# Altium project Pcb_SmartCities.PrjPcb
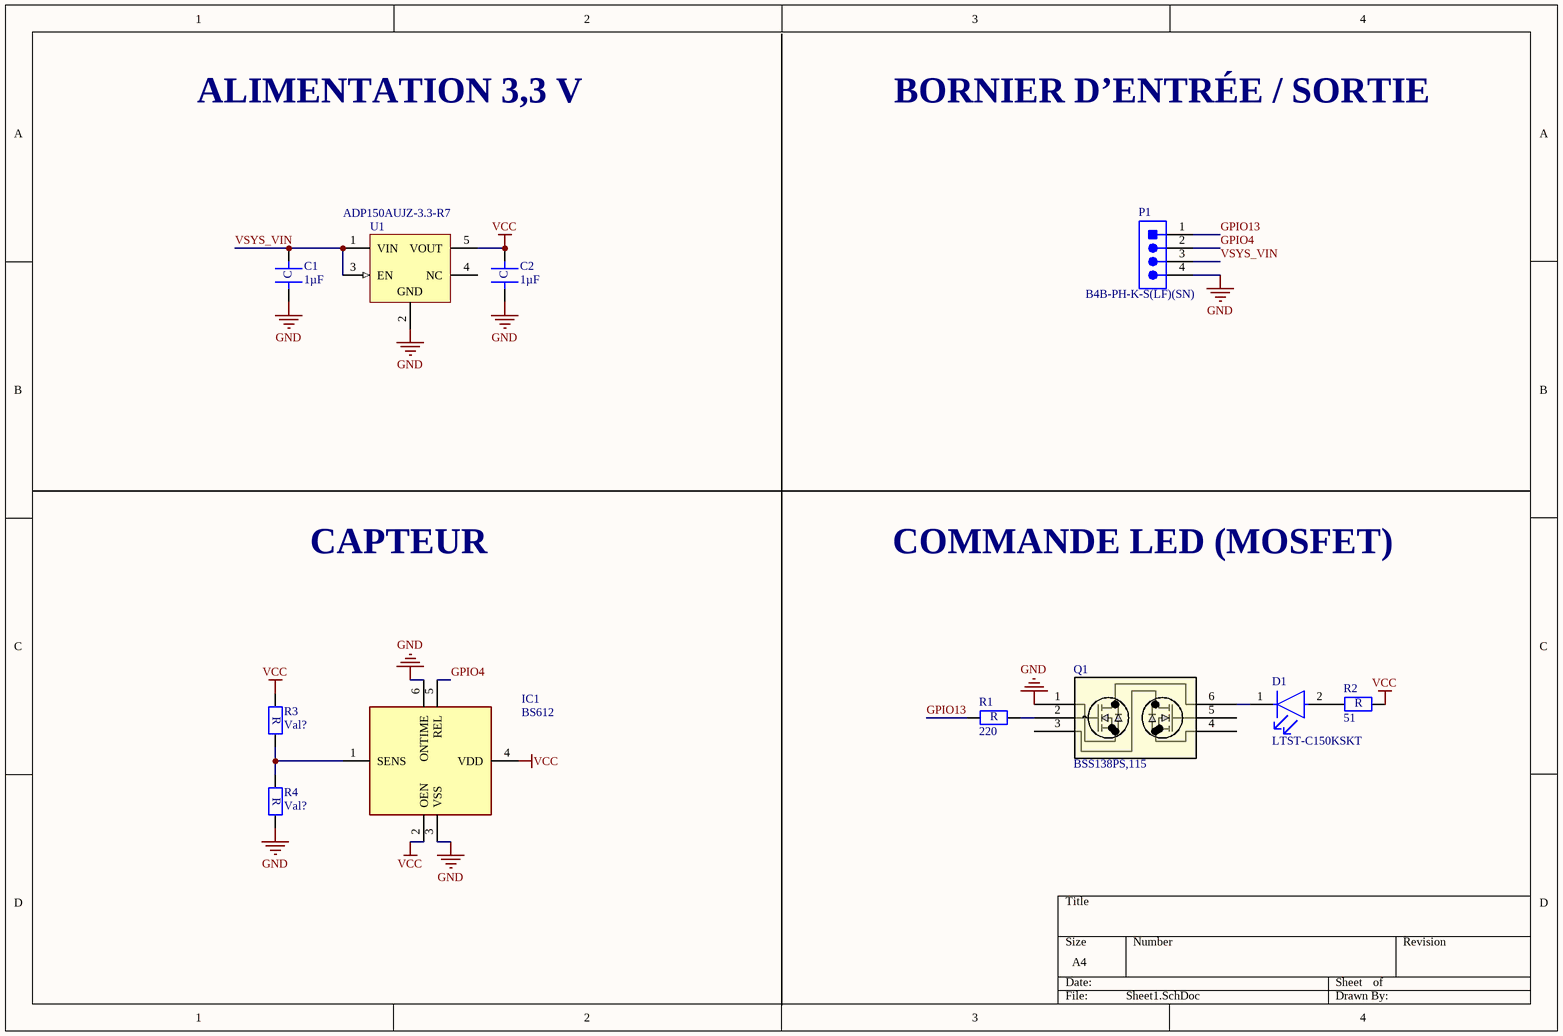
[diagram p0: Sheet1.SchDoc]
1 sheet, 11 parts. Net scope: global (net labels, ports and power ports of the same name join across sheets).
Board file: PCB1.PcbDoc

## Sheet Sheet1.SchDoc
size A4; SheetNumber: 1; SheetTotal: 1

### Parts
C1  1µF  [1206-C]
C2  1µF  [1206-C]
D1  LTST-C150KSKT  [FP-LTST-C150KSKT-MFG]
IC1  BS612  [BS612]
P1  B4B-PH-K-S(LF)(SN)  [JST-B4B-PH-K-S_V]
Q1  BSS138PS,115  [SC-88_SOT363_NEX-M]
R1  220  [1206-R]
R2  51  [1206-R]
R3  Val?  [1206-R]
R4  Val?  [1206-R]
U1  ADP150AUJZ-3.3-R7  [ADI-UJ-5_L]

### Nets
GND: C1.1 C2.1 IC1.3(VSS) IC1.6(ONTIME) P1.4 Q1.1 R4.2 U1.2(GND)
VCC: C2.2 IC1.2(OEN) IC1.4(VDD) R2.2 R3.1 U1.5(VOUT)
GPIO4: IC1.5(REL) P1.2
GPIO13: P1.1 R1.1
VSYS_VIN: C1.2 P1.3 U1.1(VIN) U1.3(EN)
NetD1_1: D1.1(C) Q1.6
NetD1_2: D1.2(A) R2.1
NetIC1_1: IC1.1(SENS) R3.2 R4.1
NetQ1_2: Q1.2 R1.2

Not connected (* = marked no-connect by the designer): Q1 3 4 5; U1 4(NC)

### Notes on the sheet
- ALIMENTATION 3,3 V
- BORNIER D’ENTRÉE / SORTIE
- CAPTEUR
- COMMANDE LED (MOSFET)

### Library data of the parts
C1 C2 = Capacitor-NP
D1 = CMP-2000-06618-2: LED YELLOW CLEAR 1206 SMD; Power Rating: 75mW; Wavelength: 588nm; Forward Current: 30mA; Test Current: 20mA; Viewing Angle: 130°; Forward Voltage: 2.4V; Luminous Intensity: 60mcd; Lens Style: Diffused; Number of Elements: 1; Reverse Voltage: 5V; Lens Color: Colorless; Dominant Wavelength: 587nm
IC1 = BS612: Integrated Circuit; Manufacturer_Name: Adafruit; Manufacturer_Part_Number: 5578
P1 = CMP-2000-05165-1: Male Header, Pitch 2 mm, 1 x 4 Position, Height 6 mm, Tail Length 3.4 mm, -25 to 85 degC, RoHS, Bulk; Manufacturer: JST; No of Positions: 4; Style/Orientation: StraightHeader/Plug; Pitch: 2mm
Q1 = BSS138PS,115: Description; Manufacturer_Name: Nexperia; Type: Transistors
R1-R4 = Resistor
U1 = CMP-0786-00394-1: Ultralow Noise, 150 mA CMOS Linear Regulator, 2.2 to 5.5 V Vin, 3.3 V Vout, Industrial, 5-pin SOT23 (UJ-5), Reel; Manufacturer: Analog Devices; Supply Current IGND @ Small Load: 10uA; Vin (min) (V): 2.2; Iout max: 150mA; Preset Vout Values (V): 3.3; Vin (max) (V): 5.5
